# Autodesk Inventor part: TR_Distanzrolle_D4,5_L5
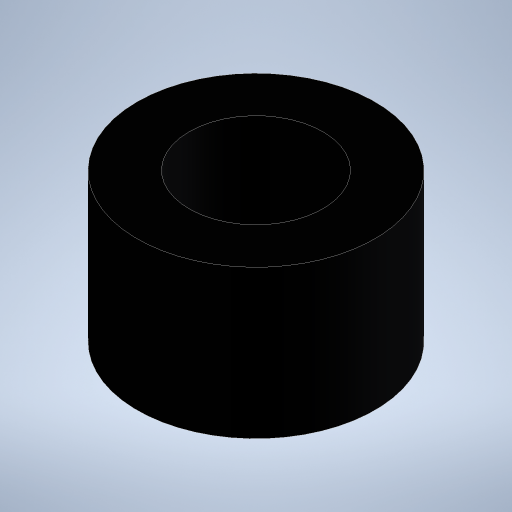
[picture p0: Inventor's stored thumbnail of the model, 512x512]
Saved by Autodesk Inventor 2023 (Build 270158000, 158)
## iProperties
Created: 2023-11
Part Number: TR_Distanzrolle_D4,5_L5
Material: PC/ABS-Kunststoff
Document SubType Name: Modeling
Designer: Admin
Density: 0.357273 g/cm^3
Appearance: Glatt - Schwarz
Author: Admin
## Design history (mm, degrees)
sketch "Skizze1"
  geometry: C1 r 2.25 at (0, 0); C2 r 4 at (0, 0); 1 further point
  constraints: 2 centre point, 2 coincident
  dimensions: "d0" = 4.5 diameter of C1; "d1" = 8 diameter of C2
extrude "Extrusion1" new body sketch "Skizze1" distance "d2" = 5; taper "d3" = 0 deg
node "Volumenkörper1"
